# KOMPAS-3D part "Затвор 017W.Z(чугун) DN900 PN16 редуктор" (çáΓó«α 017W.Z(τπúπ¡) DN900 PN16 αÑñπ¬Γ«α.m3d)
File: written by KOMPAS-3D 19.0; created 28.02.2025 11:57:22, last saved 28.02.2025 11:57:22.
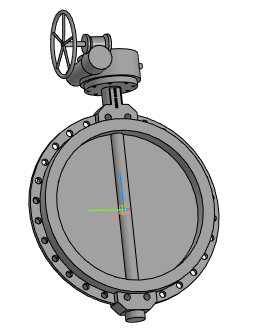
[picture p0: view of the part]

Document properties: Автор: Евгений; Полное имя файла: Затвор 017W.Z(чугун) DN900 PN16 редуктор.a3d

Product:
- Part/product: Затвор 017W.Z(чугун) DN900 PN16 редуктор
    Масса: 713.353

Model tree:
1. Операция без истории:1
